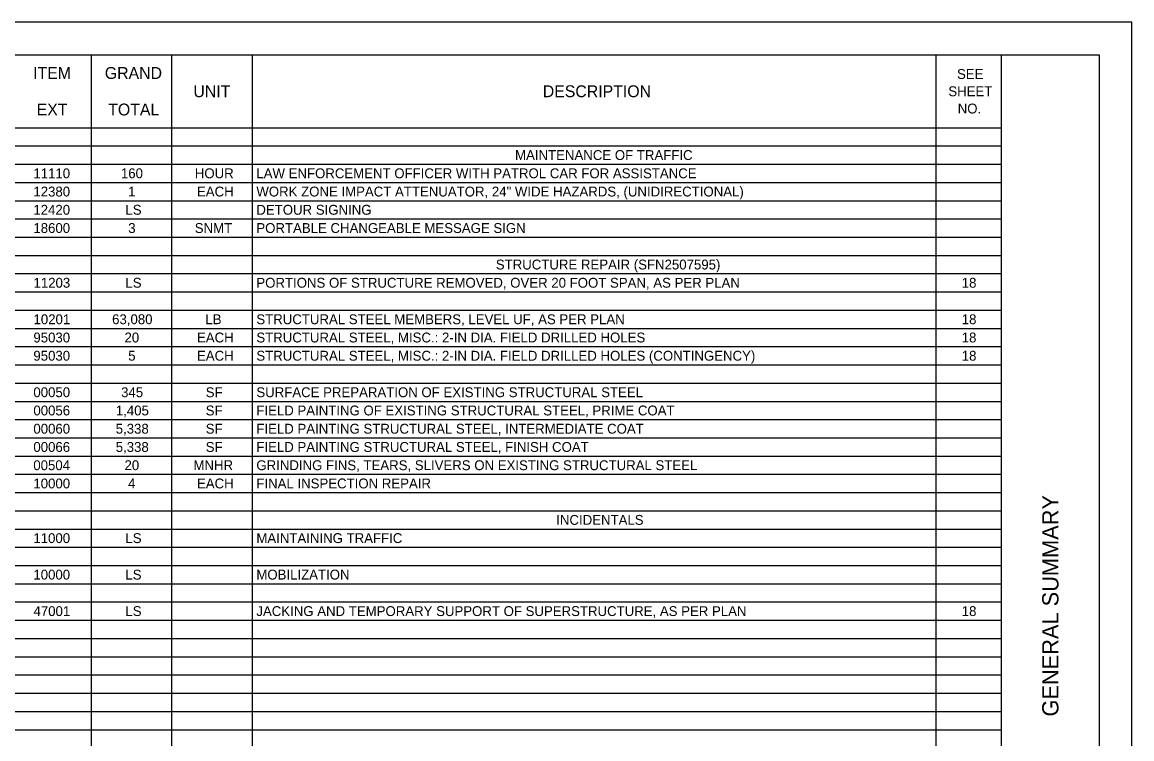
# Model space of a CAD drawing. Extents: x 0 to 34, y 0 to 22.
# Drawn here: x 16.98 to 34, y 11 to 22 of the extents above; entities that cross this region are included whole.
import ezdxf

# ---------------------------------------------------------------- set-up
doc = ezdxf.new("R2010")
doc.units = 0
for name, color, linetype in [('Default', 7, 'Continuous'), ('SH_Border', 7, 'Continuous'), ('SH_Cut_Line', 7, 'Continuous'), ('SH_Data', 7, 'Continuous')]:
    doc.layers.add(name, color=color, linetype=linetype)

msp = doc.modelspace()

# ---------------------------------------------------------------- linework, layer by layer
at = {"layer": 'Default'}
for p, q in [((1.5, 21.5), (31.998, 21.5)), ((18.033, 21.5), (18.033, 0.504)), ((19.269, 21.5), (19.269, 0.504)), ((20.504, 21.5), (20.504, 0.504)), ((30.993, 21.5), (30.993, 0.504)), ((31.998, 21.5), (31.998, 0.504)), ((1.5, 20.38), (31.998, 20.38)), ((1.5, 20.1), (31.998, 20.1)), ((1.5, 19.82), (31.998, 19.82)), ((1.5, 19.54), (31.998, 19.54)), ((1.5, 19.26), (31.998, 19.26)), ((1.5, 18.98), (31.998, 18.98)), ((1.5, 18.701), (31.998, 18.701)), ((1.5, 18.421), (31.998, 18.421)), ((1.5, 18.141), (31.998, 18.141)), ((1.5, 17.861), (31.998, 17.861)), ((1.5, 17.581), (31.998, 17.581)), ((1.5, 17.301), (31.998, 17.301)), ((1.5, 17.021), (31.998, 17.021)), ((1.5, 16.741), (31.998, 16.741)), ((1.5, 16.461), (31.998, 16.461)), ((1.5, 16.181), (31.998, 16.181)), ((1.5, 15.901), (31.998, 15.901)), ((1.5, 15.621), (31.998, 15.621)), ((1.5, 15.341), (31.998, 15.341)), ((1.5, 15.061), (31.998, 15.061)), ((1.5, 14.781), (31.998, 14.781)), ((1.5, 14.501), (31.998, 14.501)), ((1.5, 14.221), (31.998, 14.221)), ((1.5, 13.941), (31.998, 13.941)), ((1.5, 13.661), (31.998, 13.661)), ((1.5, 13.381), (31.998, 13.381)), ((1.5, 13.102), (31.998, 13.102)), ((1.5, 12.822), (31.998, 12.822)), ((1.5, 12.542), (31.998, 12.542)), ((1.5, 12.262), (31.998, 12.262)), ((1.5, 11.982), (31.998, 11.982)), ((1.5, 11.702), (31.998, 11.702)), ((1.5, 11.422), (31.998, 11.422)), ((1.5, 11.142), (31.998, 11.142))]:
    msp.add_line(p, q, dxfattribs=at)
at = {"layer": 'SH_Border'}
msp.add_line((32, 0.5), (32, 21.5), dxfattribs=at)
msp.add_lwpolyline([(1.5, 21.5), (33.5, 21.5), (33.5, 0.5), (1.5, 0.5)], close=True, dxfattribs=at)
at = {"layer": 'SH_Cut_Line'}
msp.add_lwpolyline([(0, 0), (34, 0), (34, 22), (0, 22)], close=True, dxfattribs=at)

# ---------------------------------------------------------------- texts
at = {"layer": 'Default'}
for s, height, p in [('ITEM', 0.1818, (17.144, 21.129)), ('GRAND', 0.1818, (18.244, 21.129)), ('SEE ', 0.1515, (31.318, 21.129)), ('UNIT', 0.1818, (19.603, 20.849)), ('DESCRIPTION', 0.1818, (24.963, 20.849)), ('SHEET ', 0.1515, (31.185, 20.864)), ('EXT', 0.1818, (17.198, 20.569)), ('TOTAL', 0.1818, (18.296, 20.569)), ('NO.', 0.1515, (31.329, 20.599)), ('MAINTENANCE OF TRAFFIC', 0.1515, (24.538, 19.885)), ('11110', 0.1515, (17.148, 19.605)), ('160', 0.1515, (18.491, 19.605)), ('HOUR', 0.1515, (19.625, 19.605)), ('LAW ENFORCEMENT OFFICER WITH PATROL CAR FOR ASSISTANCE', 0.1515, (20.569, 19.605)), ('12380', 0.1515, (17.148, 19.325)), ('1', 0.152, (18.602, 19.325)), ('EACH', 0.1515, (19.658, 19.325)), ('WORK ZONE IMPACT ATTENUATOR, 24" WIDE HAZARDS, (UNIDIRECTIONAL)', 0.1515, (20.569, 19.325)), ('12420', 0.1515, (17.148, 19.045)), ('LS', 0.1515, (18.56, 19.045)), ('DETOUR SIGNING', 0.1515, (20.569, 19.045)), ('18600', 0.1515, (17.148, 18.765)), ('3', 0.152, (18.603, 18.765)), ('SNMT', 0.1515, (19.624, 18.765)), ('PORTABLE CHANGEABLE MESSAGE SIGN', 0.1515, (20.569, 18.765)), ('STRUCTURE REPAIR (SFN2507595)', 0.1515, (24.243, 18.205)), ('11203', 0.1515, (17.15, 17.925)), ('LS', 0.1515, (18.56, 17.925)), ('PORTIONS OF STRUCTURE REMOVED, OVER 20 FOOT SPAN, AS PER PLAN', 0.1515, (20.569, 17.925)), ('18', 0.1515, (31.391, 17.925)), ('10201', 0.1515, (17.15, 17.365)), ('63,080', 0.1515, (18.356, 17.365)), ('LB', 0.1515, (19.787, 17.365)), ('STRUCTURAL STEEL MEMBERS, LEVEL UF, AS PER PLAN', 0.1515, (20.569, 17.365)), ('18', 0.1515, (31.391, 17.365)), ('95030', 0.1515, (17.148, 17.085)), ('20', 0.1515, (18.546, 17.085)), ('EACH', 0.1515, (19.658, 17.085)), ('STRUCTURAL STEEL, MISC.: 2-IN DIA. FIELD DRILLED HOLES', 0.1515, (20.569, 17.085)), ('18', 0.1515, (31.391, 17.085)), ('95030', 0.1515, (17.148, 16.805)), ('5', 0.152, (18.603, 16.805)), ('EACH', 0.1515, (19.658, 16.805)), ('STRUCTURAL STEEL, MISC.: 2-IN DIA. FIELD DRILLED HOLES (CONTINGENCY)', 0.1515, (20.569, 16.805)), ('18', 0.1515, (31.391, 16.805)), ('00050', 0.1515, (17.148, 16.245)), ('345', 0.1515, (18.494, 16.245)), ('SF', 0.1515, (19.792, 16.245)), ('SURFACE PREPARATION OF EXISTING STRUCTURAL STEEL', 0.1515, (20.569, 16.245)), ('00056', 0.1515, (17.148, 15.965)), ('1,405', 0.1515, (18.413, 15.965)), ('SF', 0.1515, (19.792, 15.965)), ('FIELD PAINTING OF EXISTING STRUCTURAL STEEL, PRIME COAT', 0.1515, (20.569, 15.965)), ('00060', 0.1515, (17.148, 15.685)), ('5,338', 0.1515, (18.411, 15.685)), ('SF', 0.1515, (19.792, 15.685)), ('FIELD PAINTING STRUCTURAL STEEL, INTERMEDIATE COAT', 0.1515, (20.569, 15.685)), ('00066', 0.1515, (17.148, 15.405)), ('5,338', 0.1515, (18.411, 15.405)), ('SF', 0.1515, (19.792, 15.405)), ('FIELD PAINTING STRUCTURAL STEEL, FINISH COAT', 0.1515, (20.569, 15.405)), ('00504', 0.1515, (17.147, 15.125)), ('20', 0.1515, (18.546, 15.125)), ('MNHR', 0.1515, (19.604, 15.125)), ('GRINDING FINS, TEARS, SLIVERS ON EXISTING STRUCTURAL STEEL', 0.1515, (20.569, 15.125)), ('10000', 0.1515, (17.148, 14.845)), ('4', 0.152, (18.6, 14.845)), ('EACH', 0.1515, (19.658, 14.845)), ('FINAL INSPECTION REPAIR', 0.1515, (20.569, 14.845)), ('INCIDENTALS', 0.1515, (25.17, 14.286)), ('11000', 0.1515, (17.148, 14.006)), ('LS', 0.1515, (18.56, 14.006)), ('MAINTAINING TRAFFIC', 0.1515, (20.569, 14.006)), ('10000', 0.1515, (17.148, 13.446)), ('LS', 0.1515, (18.56, 13.446)), ('MOBILIZATION', 0.1515, (20.569, 13.446)), ('47001', 0.1515, (17.15, 12.886)), ('LS', 0.1515, (18.56, 12.886)), ('JACKING AND TEMPORARY SUPPORT OF SUPERSTRUCTURE, AS PER PLAN', 0.1515, (20.569, 12.886)), ('18', 0.1515, (31.391, 12.886))]:
    msp.add_text(s, height=height, dxfattribs=at).set_placement(p)
at = {"layer": 'SH_Data'}
msp.add_text('GENERAL SUMMARY', height=0.25, rotation=90, dxfattribs=at).set_placement((32.875, 11.344))

doc.saveas('drawing.dxf')
